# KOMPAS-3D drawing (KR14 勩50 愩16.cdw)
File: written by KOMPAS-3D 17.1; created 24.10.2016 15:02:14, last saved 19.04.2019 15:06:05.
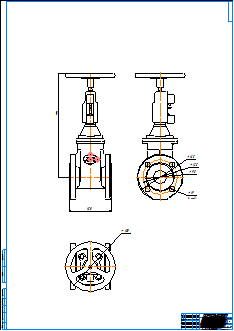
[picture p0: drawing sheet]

Sheet 1: A0, portrait

Title block, sheet 1: name: KR14 Ду50 Ру16; material: Внимание! Данный продукт является объектом авторского права ООО «Торговый Дом АДЛ». / Запрещается изменение, копирование, распространение / (в том числе путем копирования на другие сайты и ресурсы в Интернете) / или любое иное использование информации и объектов без предварительного / согласия правообладателя (ООО «Торговый Дом АДЛ»).; mass: 19,7; sheets: 1; organisation: ООО "Торговый дом АДЛ"; sheet format: A0; stored path: \\adlc.lan\data\АДЛ_ПКД\3D-модели\ADL production\Клиновые задвижки серии KR ГРАНАР\Клиновые задвижки KR14\kompas 2d\KR14 Ду50 Ру16.cdw

Views: Вид 1
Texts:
  Klimkovich
  ADL
Dimensions and other numbers on the sheet: 150; 374; 1:1; 1; 19,7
